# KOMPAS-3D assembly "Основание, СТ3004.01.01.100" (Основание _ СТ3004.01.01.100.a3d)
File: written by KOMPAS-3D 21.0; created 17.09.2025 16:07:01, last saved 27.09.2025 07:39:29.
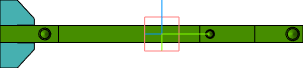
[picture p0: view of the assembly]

Document properties: Полное имя файла: C:\Users\Lutik\Yandex.Disk\Документы\Новая папка\Стапель №2\Стапель _ СТ3004.00.00.000\Опора _ СТ3004.01.00.000\3D\Кронштейн _ СТ3004.01.01.000\Основание _ СТ3004.01.01.100\Основание _ СТ3004.01.01.100.a3d; Автор: 1

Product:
- Part/product: Основание  | designation СТ3004.01.01.100
    Масса: 6.204975
    Форматы листов документа: A3
  - Component [detail]: Пластина  | designation СТ3003.01.01.102  | pos. 1  | Материал: Лист$dБ-ПН-НО-16 ГОСТ 19903-2015;Ст3сп ГОСТ 14637-89$ (density 7850 kg/m3); Масса: 0.442831; Форматы листов документа: A4; source file: ..\..\..\..\..\Стапель _ СТ3003.00.00.000\Опора _ СТ3003.01.00.000\3D\Кронштейн _ СТ3003.01.01.000\Основание _ СТ3003.01.01.100\Пластина _ СТ3003.01.01.102.m3d
  - Component [detail]: Пластина  | designation СТ3004.01.01.101  | pos. 2  | Материал: Лист$dБ-ПН-НО-25 ГОСТ 19903-2015;Ст3сп ГОСТ 14637-89$ (density 7850 kg/m3); Масса: 5.762144; Форматы листов документа: A2; source file: ..\..\..\2D\Кронштейн _ СТ3004.01.01.000\Основание _ СТ3004.01.01.100\Пластина _ СТ3004.01.01.101.cdw, Пластина _ СТ3004.01.01.101.m3d

Referenced files in C:\Users\Lutik\Yandex.Disk\Документы\Новая папка\Стапель №2\Стапель _ СТ3004.00.00.000\Опора _ СТ3004.01.00.000\3D\Кронштейн _ СТ3004.01.01.000\Основание _ СТ3004.01.01.100\: Пластина _ СТ3004.01.01.101.m3d
Referenced files in C:\Users\Lutik\Yandex.Disk\Документы\Новая папка\Стапель №2\Стапель _ СТ3003.00.00.000\Опора _ СТ3003.01.00.000\3D\Кронштейн _ СТ3003.01.01.000\Основание _ СТ3003.01.01.100\: Пластина _ СТ3003.01.01.102.m3d
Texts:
  СТ3004.01.01.100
